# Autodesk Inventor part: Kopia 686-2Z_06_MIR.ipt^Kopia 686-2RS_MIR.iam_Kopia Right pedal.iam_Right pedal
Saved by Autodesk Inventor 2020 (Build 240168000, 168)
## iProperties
Created: 2017-10
Part Number: Kopia 686-2Z_06_MIR.ipt^Kopia 686-2RS_MIR.iam_Kopia Right pedal.iam_Right pedal
Material: Ogólny
Document SubType Name: Modeling
Designer: Tomasz
Density: 1 g/cm^3
Appearance: Domyślna
Sending System: SolidWorks 2017
Last Author: Tomasz
Last Saved: 2017-10-01
Author: Tomasz
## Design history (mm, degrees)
